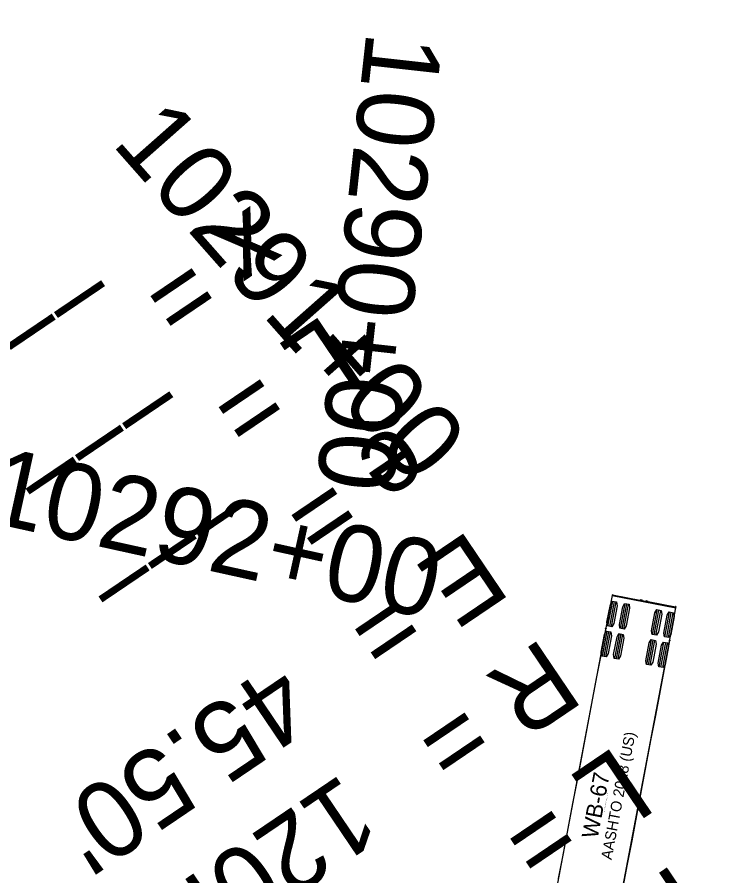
# Model space of a CAD drawing. Extents: x -69 to 14108008, y -6 to 8640172.
# Drawn here: x 14107804 to 14107898.2, y 8639717.5 to 8639829.8 of the extents above; entities that cross this region are included whole.
import ezdxf

# ---------------------------------------------------------------- set-up
doc = ezdxf.new("R2010")
doc.units = 0
for name, color, linetype in [('Alignment', 7, 'Continuous'), ('AutoTurn1', 7, 'Continuous'), ('AutoTurn2', 7, 'Continuous'), ('AutoTurn3', 7, 'Continuous'), ('AutoTurn4', 7, 'Continuous'), ('Default', 7, 'Continuous'), ('TextAlignment', 7, 'Continuous'), ('TextAlignmentLrg', 7, 'Continuous'), ('TextAlignmentSml', 7, 'Continuous')]:
    doc.layers.add(name, color=color, linetype=linetype)

msp = doc.modelspace()

# ---------------------------------------------------------------- linework, layer by layer
at = {"layer": 'Alignment'}
msp.add_arc((14107849.81, 8639782.85), 120, 80.5511, 167.6032, dxfattribs=at)
at = {"layer": 'AutoTurn1'}
for p, q in [((14107881.9, 8639754.17), (14107890.25, 8639752.59)), ((14107881.37, 8639750.19), (14107881.99, 8639753.43)), ((14107881.6, 8639750.15), (14107882.21, 8639753.39)), ((14107881.82, 8639750.1), (14107882.44, 8639753.35)), ((14107883, 8639749.88), (14107883.61, 8639753.12)), ((14107883.22, 8639749.84), (14107883.83, 8639753.08)), ((14107883.45, 8639749.8), (14107884.06, 8639753.04)), ((14107885.56, 8639753.55), (14107885.82, 8639753.5)), ((14107886.34, 8639753.4), (14107885.83, 8639753.5)), ((14107886.08, 8639753.45), (14107886.07, 8639753.38)), ((14107886.35, 8639753.4), (14107886.61, 8639753.35)), ((14107887.2, 8639749.08), (14107887.82, 8639752.33)), ((14107887.43, 8639749.04), (14107888.04, 8639752.28)), ((14107887.65, 8639749), (14107888.27, 8639752.24)), ((14107888.82, 8639748.78), (14107889.44, 8639752.02)), ((14107889.05, 8639748.73), (14107889.66, 8639751.98)), ((14107889.27, 8639748.69), (14107889.89, 8639751.93)), ((14107880.63, 8639746.26), (14107881.24, 8639749.5)), ((14107880.85, 8639746.22), (14107881.47, 8639749.46)), ((14107881.08, 8639746.17), (14107881.69, 8639749.42)), ((14107882.25, 8639745.95), (14107882.86, 8639749.19)), ((14107882.48, 8639745.91), (14107883.09, 8639749.15)), ((14107882.7, 8639745.87), (14107883.31, 8639749.11)), ((14107886.46, 8639745.15), (14107887.07, 8639748.4)), ((14107886.68, 8639745.11), (14107887.3, 8639748.35)), ((14107886.91, 8639745.07), (14107887.52, 8639748.31)), ((14107888.08, 8639744.85), (14107888.69, 8639748.09)), ((14107888.3, 8639744.8), (14107888.92, 8639748.05)), ((14107888.53, 8639744.76), (14107889.14, 8639748))]:
    msp.add_line(p, q, dxfattribs=at)
for points in [[(14107881.93, 8639754.24), (14107881.91, 8639754.24), (14107881.9, 8639754.17), (14107880.84, 8639748.6), (14107872.05, 8639702.24), (14107876.22, 8639701.44), (14107880.4, 8639700.65), (14107889.19, 8639747.02), (14107890.25, 8639752.59), (14107890.26, 8639752.66), (14107890.24, 8639752.66)], [(14107885.84, 8639753.57), (14107885.58, 8639753.62), (14107885.58, 8639753.62), (14107885.56, 8639753.55), (14107885.53, 8639753.55), (14107881.96, 8639754.23), (14107881.95, 8639754.23)], [(14107890.21, 8639752.66), (14107890.21, 8639752.66), (14107886.64, 8639753.34), (14107886.61, 8639753.35), (14107886.62, 8639753.42), (14107886.62, 8639753.42), (14107886.36, 8639753.47)], [(14107881.08, 8639749.89), (14107880.46, 8639746.61), (14107879.84, 8639743.34), (14107879.22, 8639740.07), (14107878.6, 8639736.79), (14107877.98, 8639733.52), (14107877.36, 8639730.25), (14107876.74, 8639726.97), (14107876.12, 8639723.7), (14107875.49, 8639720.43), (14107874.87, 8639717.15)], [(14107889.43, 8639748.3), (14107888.81, 8639745.03), (14107888.19, 8639741.76), (14107887.57, 8639738.48), (14107886.95, 8639735.21), (14107886.33, 8639731.94), (14107885.71, 8639728.66), (14107885.09, 8639725.39), (14107884.47, 8639722.11), (14107883.85, 8639718.84), (14107883.22, 8639715.57)]]:
    msp.add_lwpolyline(points, dxfattribs=at)
for points in [[(14107881.88, 8639750.09), (14107881.32, 8639750.2), (14107881.23, 8639750.69), (14107881.68, 8639753.02), (14107881.93, 8639753.44), (14107882.49, 8639753.34), (14107882.58, 8639752.85), (14107882.14, 8639750.51)], [(14107883.5, 8639749.79), (14107882.94, 8639749.89), (14107882.86, 8639750.38), (14107883.3, 8639752.71), (14107883.55, 8639753.13), (14107884.12, 8639753.03), (14107884.2, 8639752.54), (14107883.76, 8639750.21)], [(14107887.71, 8639748.99), (14107887.15, 8639749.09), (14107887.06, 8639749.58), (14107887.51, 8639751.91), (14107887.76, 8639752.34), (14107888.32, 8639752.23), (14107888.41, 8639751.74), (14107887.96, 8639749.41)], [(14107889.33, 8639748.68), (14107888.77, 8639748.79), (14107888.69, 8639749.27), (14107889.13, 8639751.61), (14107889.38, 8639752.03), (14107889.95, 8639751.92), (14107890.03, 8639751.44), (14107889.59, 8639749.1)], [(14107881.14, 8639746.16), (14107880.57, 8639746.27), (14107880.49, 8639746.76), (14107880.93, 8639749.09), (14107881.19, 8639749.51), (14107881.75, 8639749.41), (14107881.83, 8639748.92), (14107881.39, 8639746.58)], [(14107882.76, 8639745.86), (14107882.19, 8639745.96), (14107882.11, 8639746.45), (14107882.55, 8639748.78), (14107882.81, 8639749.2), (14107883.37, 8639749.1), (14107883.45, 8639748.61), (14107883.01, 8639746.28)], [(14107886.96, 8639745.06), (14107886.4, 8639745.16), (14107886.32, 8639745.65), (14107886.76, 8639747.98), (14107887.02, 8639748.41), (14107887.58, 8639748.3), (14107887.66, 8639747.81), (14107887.22, 8639745.48)], [(14107888.59, 8639744.75), (14107888.02, 8639744.86), (14107887.94, 8639745.34), (14107888.38, 8639747.68), (14107888.64, 8639748.1), (14107889.2, 8639747.99), (14107889.28, 8639747.51), (14107888.84, 8639745.17)]]:
    msp.add_lwpolyline(points, close=True, dxfattribs=at)
for centre, radius in [((14107881.95, 8639754.27), 0.0266), ((14107890.23, 8639752.7), 0.0266), ((14107881.08, 8639749.89), 0.0417), ((14107889.43, 8639748.3), 0.0417)]:
    msp.add_circle(centre, radius, dxfattribs=at)
for centre, radius, start, end in [((14107882.31, 8639756.22), 2.02, 259.2644, 259.9482), ((14107885.83, 8639753.53), 0.0354, 83.556, 255.7414), ((14107885.83, 8639753.53), 0.0352, 260.2388, 79.2392), ((14107886.35, 8639753.43), 0.0352, 79.2897, 258.2901), ((14107886.35, 8639753.43), 0.0353, 262.6006, 80.9503), ((14107890.23, 8639752.7), 0.0363, 278.3419, 239.5032)]:
    msp.add_arc(centre, radius, start, end, dxfattribs=at)
at = {"layer": 'AutoTurn2'}
for centre, radius, start, end in [((14107845.24, 8639780.84), 110, 84.5969, 166.0735), ((14107848.54, 8639815.69), 75, 351.3249, 84.5969)]:
    msp.add_arc(centre, radius, start, end, dxfattribs=at)
at = {"layer": 'AutoTurn3'}
msp.add_arc((14107855.74, 8639781.86), 120, 80.5511, 167.6032, dxfattribs=at)
at = {"layer": 'AutoTurn4'}
msp.add_arc((14107843.08, 8639794.35), 120, 88.0371, 167.902, dxfattribs=at)
at = {"layer": 'Default'}
msp.add_arc((14107849.81, 8639782.85), 120, 80.5511, 167.6032, dxfattribs=at)

# ---------------------------------------------------------------- texts
at = {"layer": 'AutoTurn1'}
for s, height, p in [('AASHTO 2018 (US)', 1.4167, (14107881.83, 8639719.55)), ('WB-67', 2.125, (14107880, 8639722.29)), ('(c) 2023 Transoft Solutions, Inc. All rights reserved.', 0.085, (14107880.88, 8639725.76))]:
    msp.add_text(s, height=height, rotation=79.2644, dxfattribs=at).set_placement(p)
at = {"layer": 'TextAlignment'}
for s, p in [('x = ___', (14107834.68, 8639805.22)), ('L = ___', (14107844.23, 8639791.11)), ('e = ___ ', (14107853.77, 8639777)), ('E = ', (14107863.32, 8639762.89)), ('R = ', (14107872.86, 8639748.78)), ("45.50'", (14107838.07, 8639745.81)), ('L = ', (14107882.4, 8639734.67)), ("120.00'", (14107846.63, 8639731.03)), ('T = ', (14107891.95, 8639720.56))]:
    msp.add_text(s, height=10.02, rotation=214.0771, dxfattribs=at).set_placement(p)
at = {"layer": 'TextAlignmentLrg'}
msp.add_text('10290+00', height=10.02, rotation=263.6879, dxfattribs=at).set_placement((14107849.78, 8639828.12))
at = {"layer": 'TextAlignmentSml'}
for s, rotation, p in [('10290+00', 263.6879, (14107849.78, 8639828.12)), ('10291+00', 311.4344, (14107816.28, 8639813.27)), ('10292+00', 347.6032, (14107799.58, 8639763.93))]:
    msp.add_text(s, height=10.02, rotation=rotation, dxfattribs=at).set_placement(p)

doc.saveas('drawing.dxf')
